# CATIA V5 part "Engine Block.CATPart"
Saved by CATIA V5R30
Part number: Part1
Bounding box of the stored display mesh (mm): x 0 to 150, y 0 to 40, z 0 to 43
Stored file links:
  D:\PROJECTS\CATIA V56R 2020\Resources\Parts File\c19_catia_v5_6r2020_inp\c19_catia_v5_6r2020_inp\c19_catia_v5_6r2020_inp\C19_tut_04.CATPart\Engine Block.CATPart
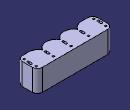
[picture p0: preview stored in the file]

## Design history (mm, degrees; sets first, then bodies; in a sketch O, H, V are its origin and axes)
Body1 (main body)
  Sketch1 on xy-plane, origin (0, 0, 0), H (1, 0, 0), V (0, 1, 0)
    line L1 (10, 0) -> (140, 0)
    line L2 (150, 10) -> (150, 30)
    line L3 (140, 40) -> (10, 40)
    line L4 (0, 30) -> (0, 10)
    arc A1 centre (10, 10) radius 10 from (10, 0) to (0, 10) cw
    arc A2 centre (140, 10) radius 10 from (140, 0) to (150, 10) ccw
    arc A3 centre (140, 30) radius 10 from (150, 30) to (140, 40) ccw
    arc A4 centre (10, 30) radius 10 from (10, 40) to (0, 30) ccw
    radius A1 = 10
    radius A2 = 10
    radius A3 = 10
    radius A4 = 10
    distance L2 L4 = 150
    distance L3 L1 = 40
    horizontal: L1 H, L3 H
    vertical: L2 V, L4 V
    coincidence: L1 O, L4 O
    tangency: A1 L1, A1 L4, A2 L1, A2 L2, A3 L2, A3 L3, A4 L3, A4 L4
  Pad1: profile Sketch1, direction (0, 0, 1), length 43
  Sketch2 on xy-plane, origin (0, 0, 0), H (1, 0, 0), V (0, 1, 0)
    circle A1 centre (22.5, 20) radius 12.5
    point P1 (22.5, 20)
    point P2 (57.5, 20)
    circle A2 centre (57.5, 20) radius 12.5
    point P3 (92.5, 20)
    circle A3 centre (92.5, 20) radius 12.5
    point P4 (127.5, 20)
    circle A4 centre (127.5, 20) radius 12.5
    reference projected line E1 (140, 40) -> (10, 40) from edge [face of Pad1 from Sketch1.L3 | end face of Pad1]
    construction line L1 (22.5, 20) -> (160.4972, 20)
    axis line L2 (75, 83.7885) -> (75, -11.6317)
    reference projected line E2 (150, 10) -> (150, 30) from edge [face of Pad1 from Sketch1.L2 | end face of Pad1]
    reference projected line E3 (0, 30) -> (0, 10) from edge [face of Pad1 from Sketch1.L4 | end face of Pad1]
    radius A2 = 12.5
    radius A3 = 12.5
    radius A4 = 12.5
    distance P1 E1 = 20
    distance P1 P2 = 35
    distance P2 P3 = 35
    distance P3 P4 = 35
    horizontal: L1 H
    coincidence: L1 P2, L1 P3, P4 L1
    symmetry: E2 E3 L2, A4 A1 L2
  Pocket1: profile Sketch2, direction (0, 0, 1), length 40
  Sketch3 on start face of Pad1, origin (0, 0, 0), H (1, 0, 0), V (0, -1, 0)
    arc A1 centre (22.5, -20) radius 20 from (40, -10.3175) to (22.4999, 0) ccw
    arc A2 centre (57.5, -20) radius 20 from (57.5, 0) to (40, -10.3175) ccw
    reference projected circle E1 centre (57.5, -20) radius 12.5 from edge [face of Pocket1 from Sketch2.A2 | start face of Pad1]
    reference projected circle E2 centre (22.5, -20) radius 12.5 from edge [face of Pocket1 from Sketch2.A1 | start face of Pad1]
    line L1 (22.4999, 0) -> (57.5, 0)
    radius A1 = 20
    radius A2 = 20
    concentricity: A2 E1, E2 A1
    fix: L1
  Pocket2: profile Sketch3, direction (0, 0, 1), through (limit type 6)
  RectPattern1: of Pocket2, direction 1 instances 3, spacing 35, along edge [start face of Pad1 | face of Pad1 from Sketch1.L1]
  Sketch4 on start face of Pad1, origin (0, 0, 0), H (1, 0, 0), V (0, -1, 0)
    circle A1 centre (6, -32) radius 2
    point P2 (40, -32)
    circle A2 centre (40, -32) radius 2
    point P3 (75, -32)
    circle A3 centre (75, -32) radius 2
    point P4 (110, -32)
    circle A4 centre (110, -32) radius 2
    circle A5 centre (144, -32) radius 2
    construction line L1 (6, -32) -> (144, -32)
    construction line L2 (40, 4.6658) -> (40, -59.1562)
    reference projected point E1 (40, -10.3175) from vertex [start face of Pad1 | face of Pocket2 from Sketch3.A2 | face of Pocket2 from Sketch3.A1]
    construction line L3 (110, 9.612) -> (110, -55.4864)
    construction line L4 (75, 52.0631) -> (75, -75.4722)
    reference projected line E2 (0, -30) -> (0, -10) from edge [start face of Pad1 | face of Pad1 from Sketch1.L4]
    reference projected line E3 (150, -10) -> (150, -30) from edge [start face of Pad1 | face of Pad1 from Sketch1.L2]
    reference projected point E4 (110, -10.3175) from vertex [face of RectPattern1 | face of RectPattern1 | start face of Pad1]
    axis line L5 (-9.2648, -20) -> (155.2665, -20)
    reference projected line E5 (10, 0) -> (140, 0) from edge [start face of Pad1 | face of Pad1 from Sketch1.L1]
    reference projected line E6 (140, -40) -> (10, -40) from edge [start face of Pad1 | face of Pad1 from Sketch1.L3]
    circle A6 centre (6, -8) radius 2
    circle A7 centre (144, -8) radius 2
    radius A1 = 2
    radius A2 = 2
    radius A3 = 2
    radius A4 = 2
    horizontal: L1 H, L5 H
    coincidence: P4 L1, P3 L1, P2 L1, L2 E1, P2 L2, P4 L3, P3 L4, L3 E4
    vertical: L2 V, L3 V, L4 V
    symmetry: E2 E3 L4, A1 A5 L4, E5 E6 L5, A1 A6 L5, A5 A7 L5
    fix: A1
  Pocket3: profile Sketch4, direction (0, 0, 1), through (limit type 6)
  Sketch5 on start face of Pad1, origin (0, 0, 0), H (1, 0, 0), V (0, -1, 0)
    construction line L1 (40, -22.3175) -> (40, -16.3175)
    point P2 (40, -16.3175)
    line L2 (38, -22.3175) -> (38, -16.3175)
    line L3 (42, -16.3175) -> (42, -22.3175)
    arc A1 centre (40, -16.3175) radius 2 from (38, -16.3175) to (42, -16.3175) cw
    arc A2 centre (40, -22.3175) radius 2 from (42, -22.3175) to (38, -22.3175) cw
    point P3 (38, -22.3175)
    point P4 (38, -16.3175)
    point P5 (42, -16.3175)
    point P6 (42, -22.3175)
    reference projected point E1 (40, -10.3175) from vertex [start face of Pad1 | face of Pocket2 from Sketch3.A2 | face of Pocket2 from Sketch3.A1]
    reference projected point E2 (40, -10.3175) from vertex [start face of Pad1 | face of Pocket2 from Sketch3.A2 | face of Pocket2 from Sketch3.A1]
    point P7 (75, -16.3175)
    point P8 (75, -22.3175)
    construction line L4 (75, -22.3175) -> (75, -16.3175)
    point P9 (73, -22.3175)
    point P10 (73, -16.3175)
    point P11 (77, -16.3175)
    point P12 (77, -22.3175)
    line L5 (73, -22.3175) -> (73, -16.3175)
    line L6 (77, -16.3175) -> (77, -22.3175)
    arc A3 centre (75, -16.3175) radius 2 from (73, -16.3175) to (77, -16.3175) cw
    arc A4 centre (75, -22.3175) radius 2 from (77, -22.3175) to (73, -22.3175) cw
    reference projected point E3 (75, -10.3175) from vertex [face of RectPattern1 | face of RectPattern1 | start face of Pad1]
    construction line L7 (110, -22.3175) -> (110, -16.3175)
    point P15 (112, -22.3175)
    point P16 (112, -16.3175)
    point P17 (108, -16.3175)
    point P18 (108, -22.3175)
    line L8 (112, -22.3175) -> (112, -16.3175)
    line L9 (108, -16.3175) -> (108, -22.3175)
    arc A5 centre (110, -16.3175) radius 2 from (112, -16.3175) to (108, -16.3175) ccw
    arc A6 centre (110, -22.3175) radius 2 from (108, -22.3175) to (112, -22.3175) ccw
    reference projected point E4 (75, -10.3175) from vertex [face of RectPattern1 | face of RectPattern1 | start face of Pad1]
    axis line L10 (40, -22.3175) -> (110, -22.3175)
    construction line L11 (5, -22.3175) -> (5, -16.3175)
    point P21 (7, -22.3175)
    point P22 (7, -16.3175)
    point P23 (3, -16.3175)
    point P24 (3, -22.3175)
    line L12 (7, -22.3175) -> (7, -16.3175)
    line L13 (3, -16.3175) -> (3, -22.3175)
    arc A7 centre (5, -16.3175) radius 2 from (7, -16.3175) to (3, -16.3175) ccw
    arc A8 centre (5, -22.3175) radius 2 from (3, -22.3175) to (7, -22.3175) ccw
    construction line L14 (145, -22.3175) -> (145, -16.3175)
    point P27 (147, -22.3175)
    point P28 (147, -16.3175)
    point P29 (143, -16.3175)
    point P30 (143, -22.3175)
    line L15 (147, -22.3175) -> (147, -16.3175)
    line L16 (143, -16.3175) -> (143, -22.3175)
    arc A9 centre (145, -16.3175) radius 2 from (147, -16.3175) to (143, -16.3175) ccw
    arc A10 centre (145, -22.3175) radius 2 from (143, -22.3175) to (147, -22.3175) ccw
    distance L1 L2 = 2
    length L1 = 6
    distance P2 E2 = 6
    distance P7 E4 = 6
    radius A3 = 2
    distance L5 L6 = 4
    vertical: L1 V
    tangency: A1 L2, A2 L2, A1 L3, A2 L3
    coincidence: L1 E1, L4 E3, L10 P8
    symmetry: L1 L7 L4, P3 P15 L4, P4 P16 L4, P5 P17 L4, P6 P18 L4, L2 L8 L4, L3 L9 L4, A1 A5 L4, A2 A6 L4, L4 L11 L1, P9 P21 L1, P10 P22 L1, P11 P23 L1, P12 P24 L1, L5 L12 L1, L6 L13 L1, A3 A7 L1, A4 A8 L1, L4 L14 L7, P9 P27 L7, P10 P28 L7, P11 P29 L7, P12 P30 L7, L5 L15 L7, L6 L16 L7, A3 A9 L7, A4 A10 L7
    horizontal: L10 H
  Pocket4: profile Sketch5, direction (0, 0, 1), through (limit type 6)
  Sketch6 on start face of Pad1, origin (0, 0, 0), H (1, 0, 0), V (0, -1, 0)
    construction line L1 (-2.1155, -20) -> (152.3983, -20)
    reference projected line E1 (10, 0) -> (140, 0) from edge [start face of Pad1 | face of Pad1 from Sketch1.L1]
    reference projected line E2 (140, -40) -> (10, -40) from edge [start face of Pad1 | face of Pad1 from Sketch1.L3]
    circle A1 centre (22, -4) radius 1.5
    point P3 (22, -4)
    circle A2 centre (22, -36) radius 1.5
    construction line L2 (40, 18.8361) -> (40, -51.6721)
    reference projected point E3 (40, -10.3175) from vertex [start face of Pad1 | face of RectPattern1 | face of Pocket2 from Sketch3.A1]
    circle A3 centre (58, -4) radius 1.5
    axis line L3 (75, 12.6867) -> (75, -50.2038)
    reference projected point E4 (75, -10.3175) from vertex [face of RectPattern1 | face of RectPattern1 | start face of Pad1]
    circle A4 centre (58, -36) radius 1.5
    circle A5 centre (128, -4) radius 1.5
    circle A6 centre (128, -36) radius 1.5
    circle A7 centre (92, -36) radius 1.5
    circle A8 centre (92, -4) radius 1.5
    radius A1 = 1.5
    distance P3 V = 22
    distance P3 L1 = 16
    horizontal: L1 H
    symmetry: E1 E2 L1, A1 A2 L1, A1 A3 L2, A2 A4 L2, A1 A5 L3, A2 A6 L3, A4 A7 L3, A3 A8 L3
    vertical: L2 V, L3 V
    coincidence: E3 L2, L3 E4
  Pocket5: profile Sketch6, direction (0, 0, 1), length 10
